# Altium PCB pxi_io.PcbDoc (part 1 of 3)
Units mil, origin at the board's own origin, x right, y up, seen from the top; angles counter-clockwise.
Board outline 6300 x 3935 mil, 2 copper layers (Top Layer, Bottom Layer); 271 components, 388 nets, 1544 pads, 249 vias.
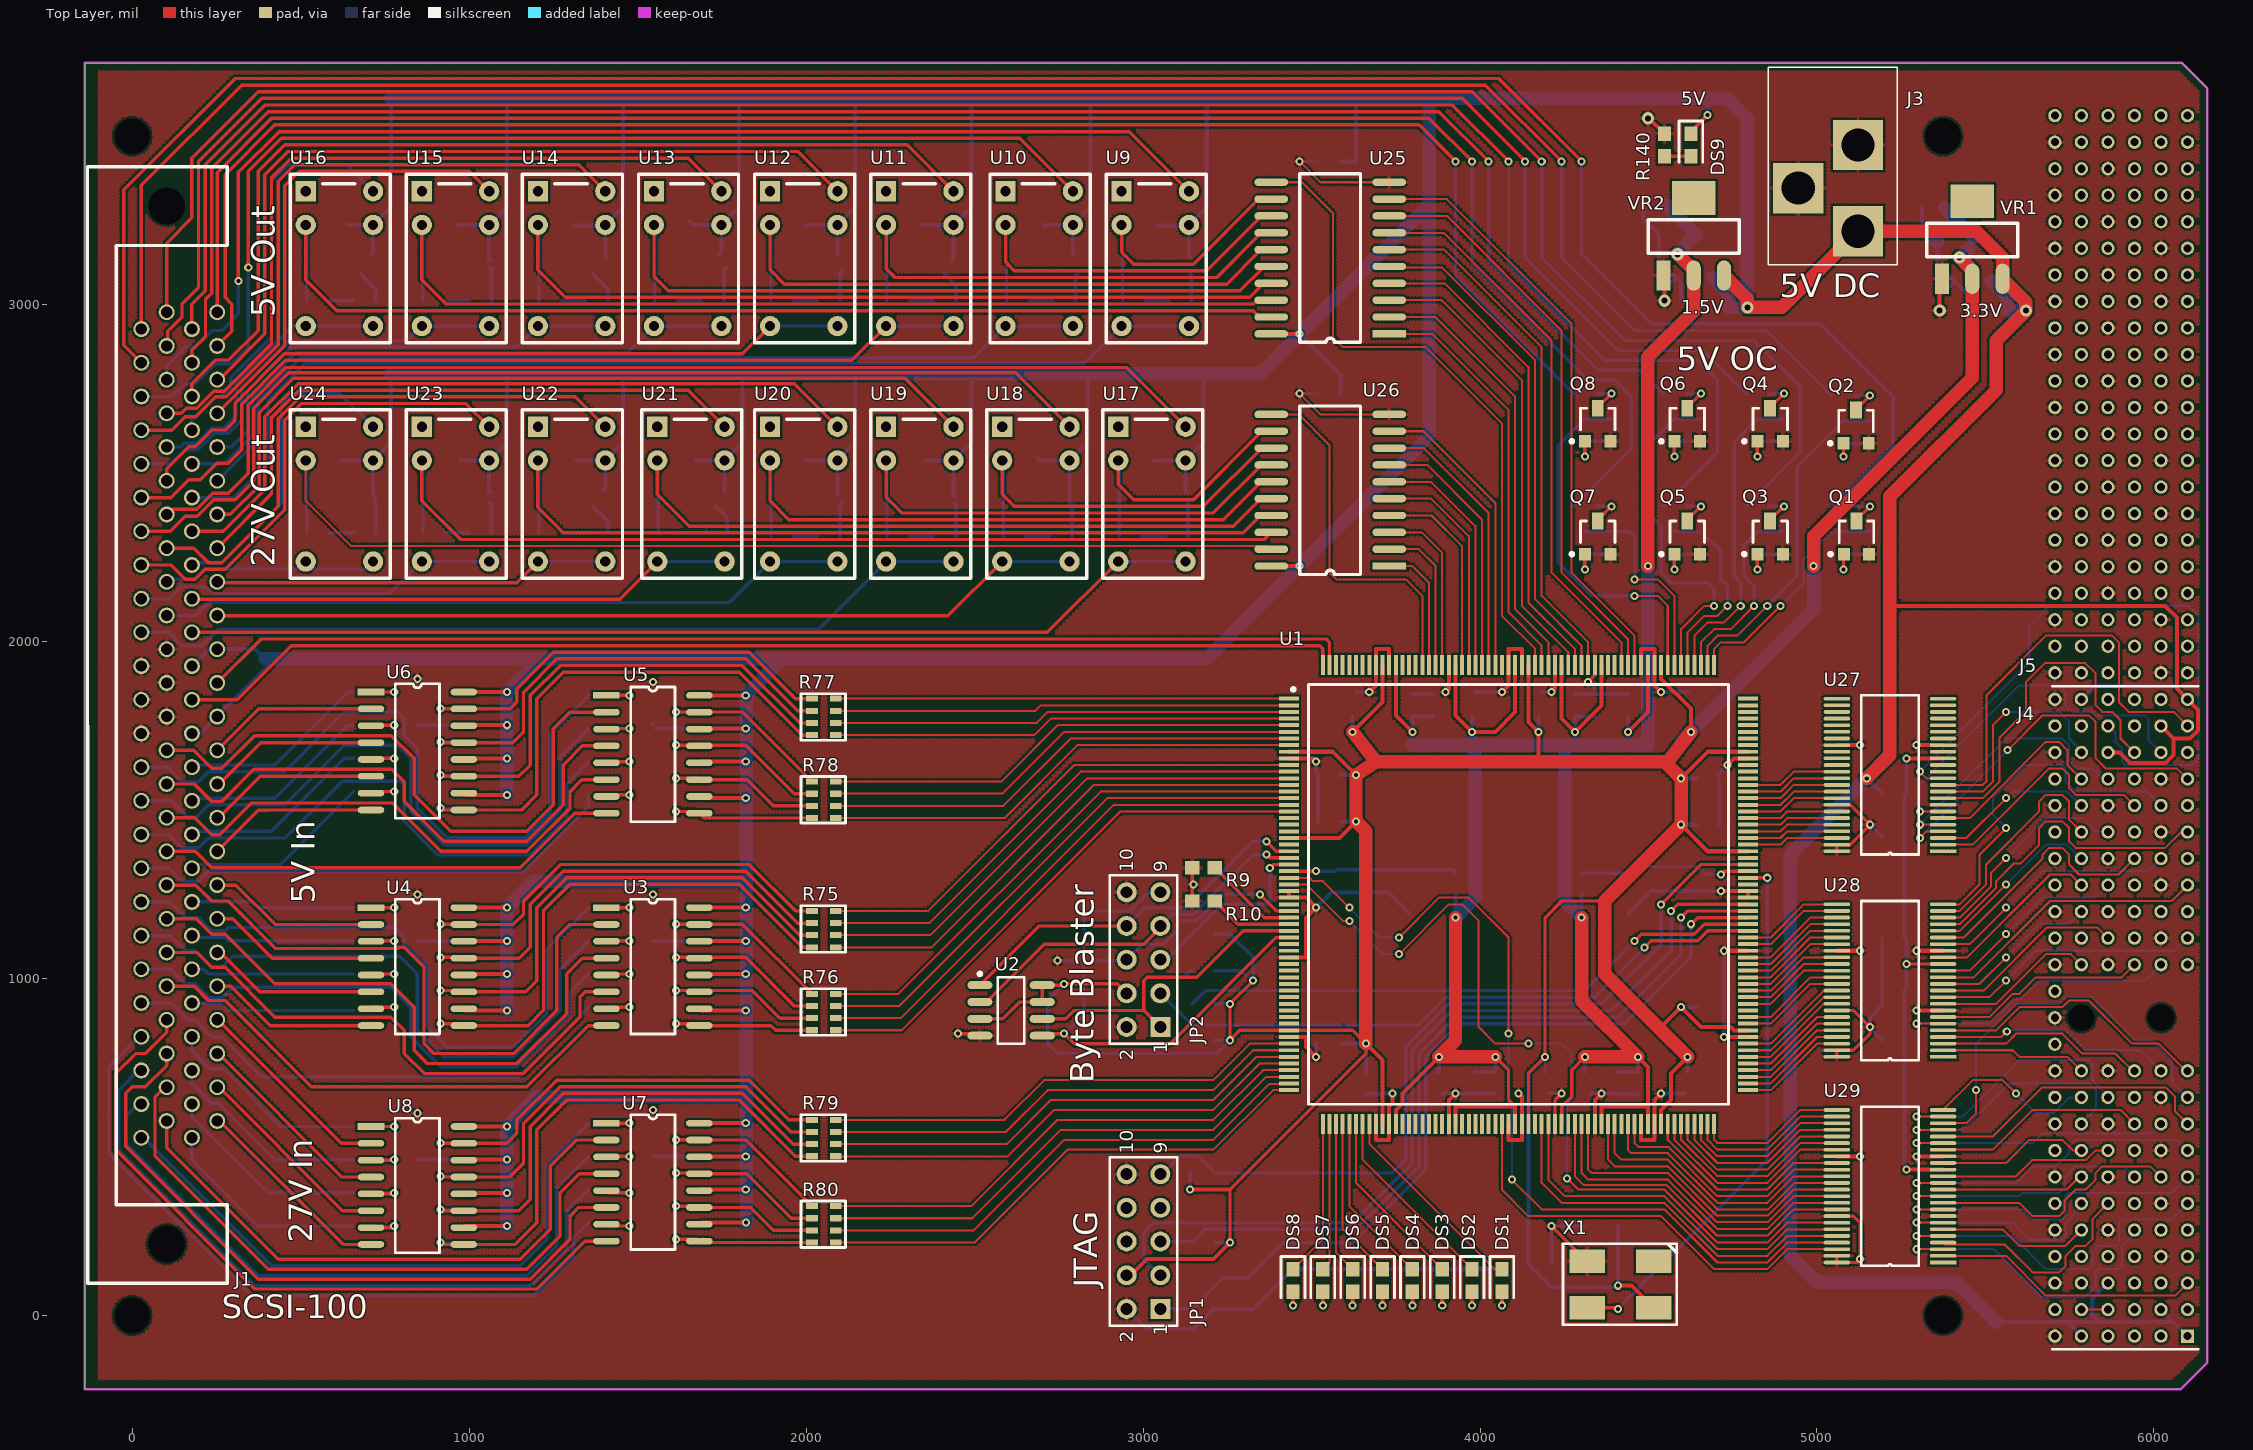
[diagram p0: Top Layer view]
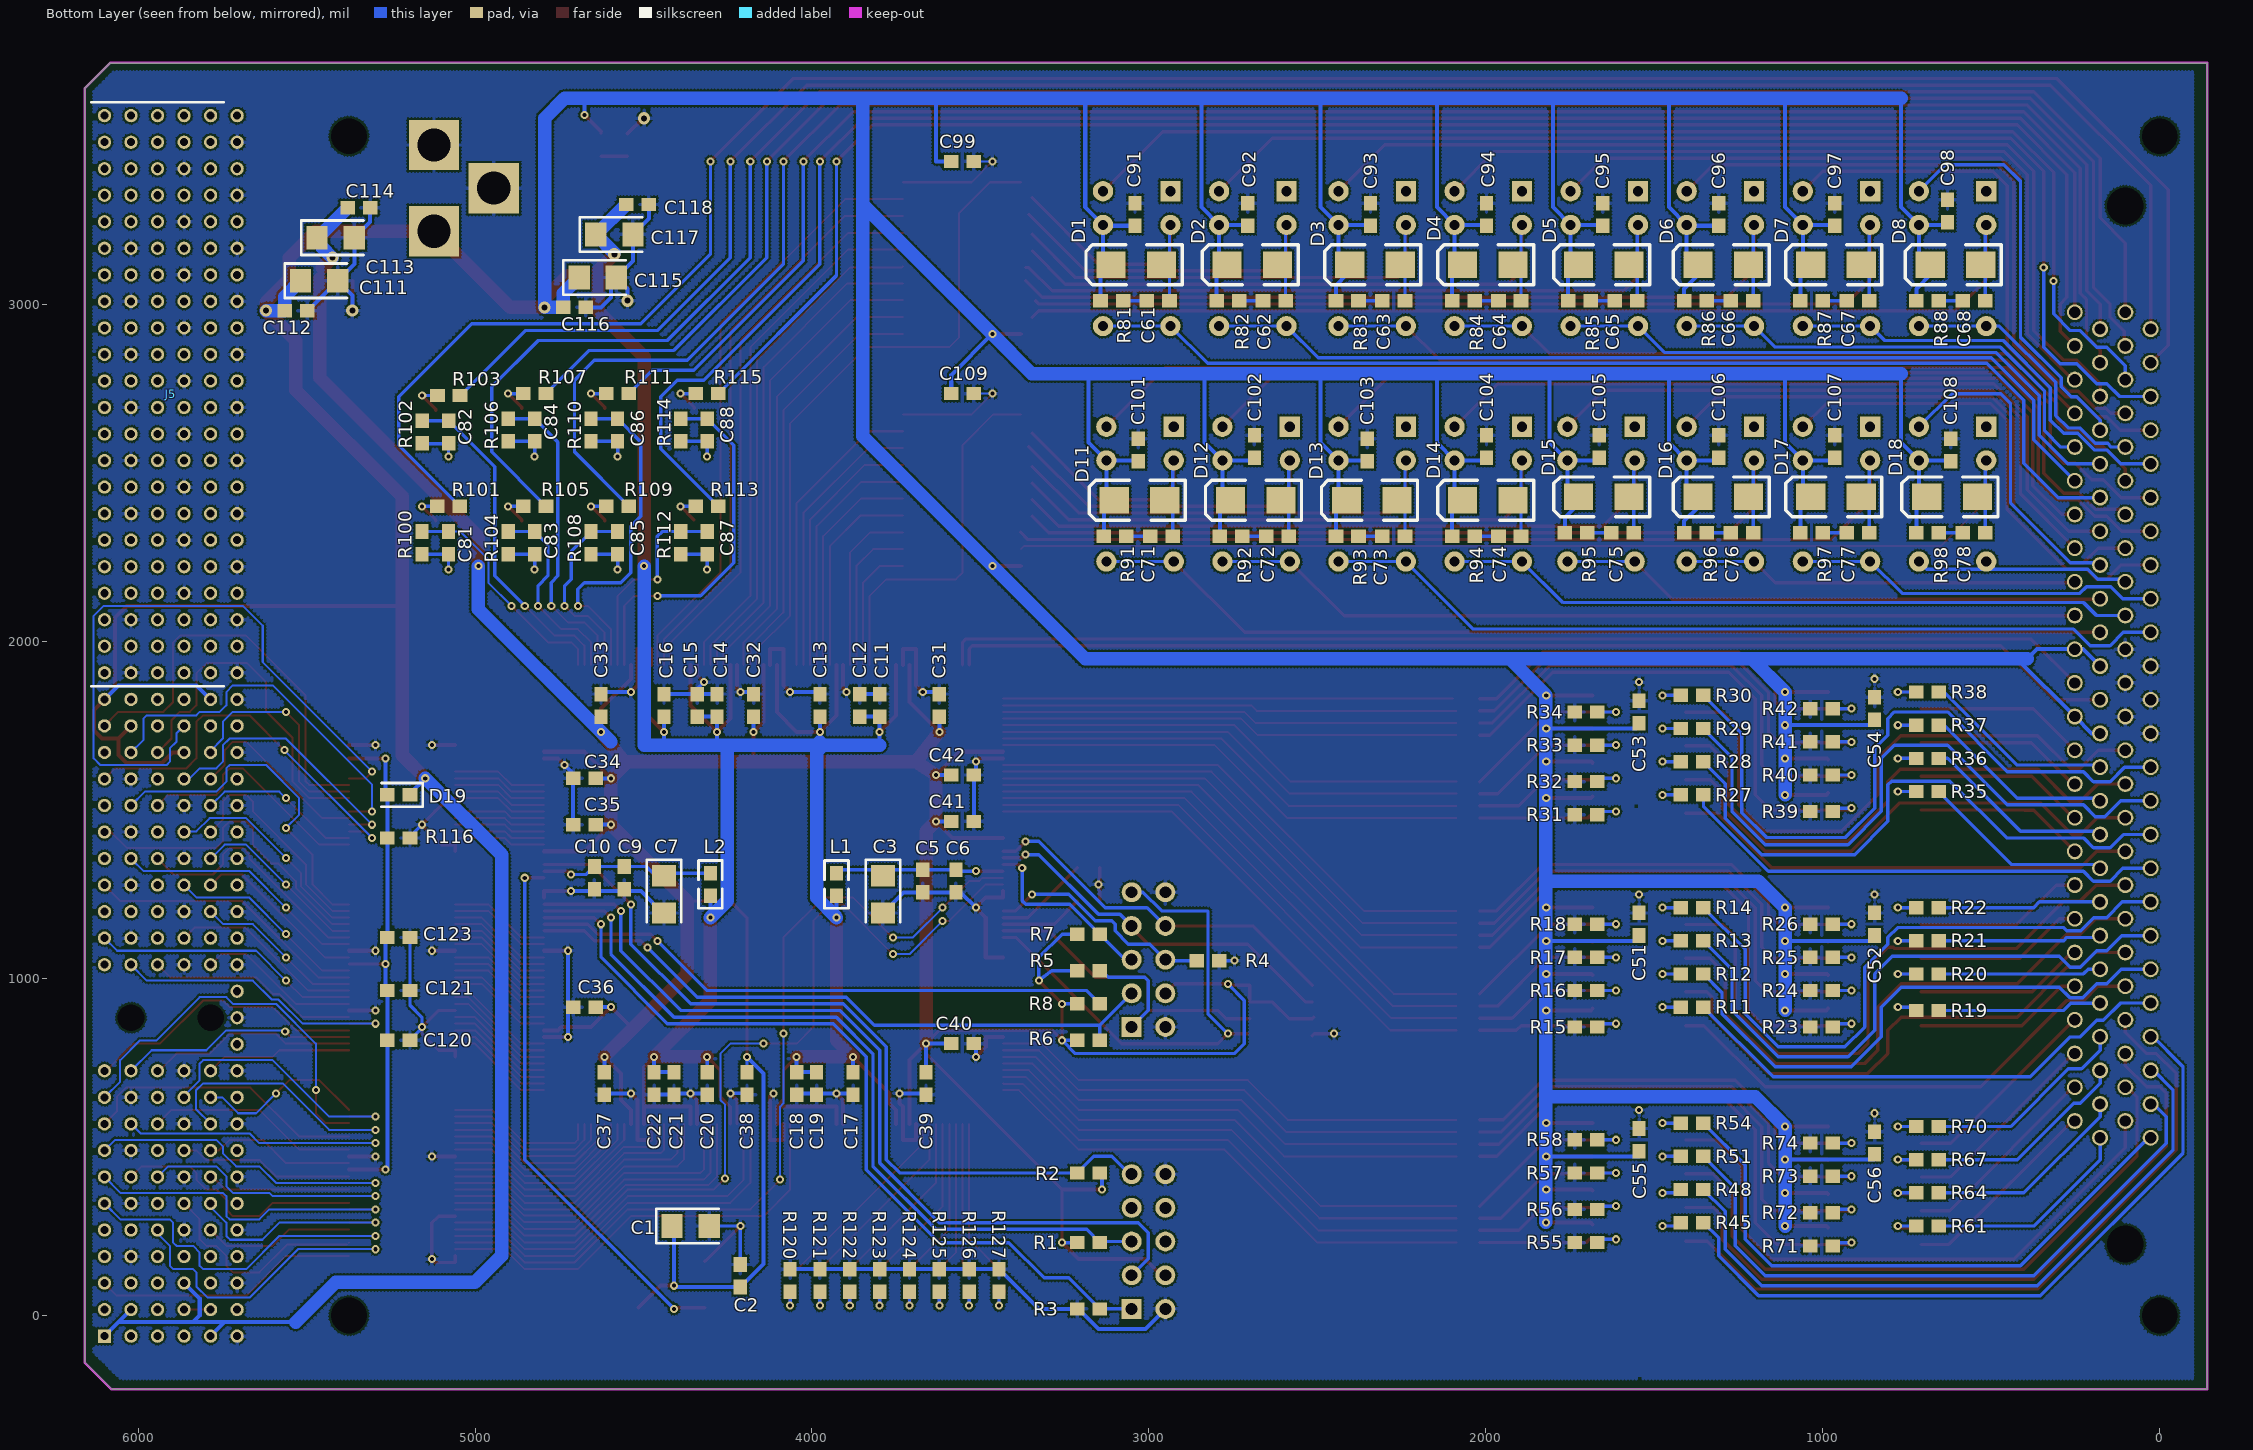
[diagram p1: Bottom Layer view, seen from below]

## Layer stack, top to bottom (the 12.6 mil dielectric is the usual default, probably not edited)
Top Layer: signal copper 1.4
Dielectric: core 12.6, FR-4, Dk 4.8
Bottom Layer: signal copper 1.4

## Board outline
-141.34,3717.05 6083.66,3717.05 6158.66,3642.05 6158.66,3637.05 6158.66,-137.95 6078.66,-217.95 -141.34,-217.95

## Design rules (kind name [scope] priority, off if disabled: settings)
Clearance [All] p1: gap=6
ComponentClearance [All] p1: gap=0 collisioncheckmode=3 verticalgap=10 showdistances=FALSE
FabricationTestPointUsage TestPointUsage [All] p1: valid=0 allowmultiple=FALSE
FabricationTestpoint Testpoint [All] p1: side=3 testpointundercomponent=TRUE minsize=40 maxsize=100 preferedsize=60 minholesize=0 maxholesize=40 preferedholesize=32 testpointgrid=1 allowsidetop=TRUE allowsidebottom=TRUE usegrid=TRUE gridtolerance=0.01
PolygonConnect [All] p1: connectstyle=Relief reliefconductorwidth=10 reliefentries=4 polygonreliefangle="90 Angle"
RoutingVias [All] p1: holewidth=28 width=50 viastyle="Through Hole" minholewidth=12 minwidth=24 maxholewidth=28 maxwidth=50
SilkscreenOverComponentPads [All] p1: minsilkscreentomaskgap=10
SolderMaskExpansion [All] p1: expansion=4
Width [All] p1: maxlimit=40 minlimit=6 preferedwidth=6
24 further rules are at their usual default settings.

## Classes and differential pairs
component class pxi_io: J1
component class pxi: C111 C112 C113 C114 C115 C116 C117 C118 C120 C121 C123 D19 DS9 J3 J4 J5 R116 R140 U27 U28 U29 VR1 VR2
component class fpga: C1 C2 C3 C5 C6 C7 C9 C10 C11 C12 C13 C14 C15 C16 C17 C18 C19 C20 C21 C22 C31 C32 C33 C34 C35 C36 C37 C38 C39 C40 C41 C42 DS1 DS2 DS3 DS4 DS5 DS6 DS7 DS8 JP1 JP2 L1 L2 R1 R2 R3 R4 R5 R6 R7 R8 R9 R10 R120 R121 R122 R123 R124 R125 R126 R127 U1 U2 X1
component class digit_out: C61 C62 C63 C64 C65 C66 C67 C68 C71 C72 C73 C74 C75 C76 C77 C78 C81 C82 C83 C84 C85 C86 C87 C88 C91 C92 C93 C94 C95 C96 C97 C98 C99 C101 C102 C103 C104 C105 C106 C107 C108 C109 D1 D2 D3 D4 D5 D6 D7 D8 D11 D12 D13 D14 D15 D16 D17 D18 Q1 Q2 Q3 Q4 Q5 Q6 Q7 Q8 R81 R82 R83 R84 R85 R86 R87 R88 R91 R92 R93 R94 R95 R96 R97 R98 R100 R101 R102 R103 R104 R105 R106 R107 R108 R109 R110 R111 R112 R113 R114 R115 U9 U10 U11 U12 U13 U14 U15 U16 U17 U18 U19 U20 U21 U22 U23 U24 U25 U26
component class digit_in: C51 C52 C53 C54 C55 C56 R11 R12 R13 R14 R15 R16 R17 R18 R19 R20 R21 R22 R23 R24 R25 R26 R27 R28 R29 R30 R31 R32 R33 R34 R35 R36 R37 R38 R39 R40 R41 R42 R45 R48 R51 R54 R55 R56 R57 R58 R61 R64 R67 R70 R71 R72 R73 R74 R75 R76 R77 R78 R79 R80 U3 U4 U5 U6 U7 U8

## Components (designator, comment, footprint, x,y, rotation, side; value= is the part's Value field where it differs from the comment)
C1 "Cap Pol3" CC3216-1206 4360.24,265.75 r180 bottom
C2 "Cap Semi" 1608[0603] 4212.6,118.11 r270 bottom
C3 "Cap Pol3" CC3216-1206 3789.37,1250 r270 bottom
C5 "Cap Semi" 1608[0603] 3671.26,1289.37 r90 bottom
C6 "Cap Semi" 1608[0603] 3572.83,1289.37 r90 bottom
C7 "Cap Pol3" CC3216-1206 4438.98,1250 r270 bottom
C9 "Cap Semi" 1608[0603] 4557.09,1299.21 r90 bottom
C10 "Cap Semi" 1608[0603] 4645.67,1299.21 r90 bottom
C11 "Cap Semi" 1608[0603] 3799.21,1811.02 r270 bottom
C12 "Cap Semi" 1608[0603] 3858.27,1811.02 r270 bottom
C13 "Cap Semi" 1608[0603] 3976.38,1811.02 r270 bottom
C14 "Cap Semi" 1608[0603] 4281.5,1811.02 r270 bottom
C15 "Cap Semi" 1608[0603] 4340.55,1811.02 r270 bottom
C16 "Cap Semi" 1608[0603] 4438.98,1811.02 r270 bottom
C17 "Cap Semi" 1608[0603] 3877.95,688.98 r90 bottom
C18 "Cap Semi" 1608[0603] 4045.28,688.98 r90 bottom
C19 "Cap Semi" 1608[0603] 3986.22,688.98 r90 bottom
C20 "Cap Semi" 1608[0603] 4311.02,688.98 r90 bottom
C21 "Cap Semi" 1608[0603] 4409.45,688.98 r90 bottom
C22 "Cap Semi" 1608[0603] 4468.5,688.98 r90 bottom
C31 "Cap Semi" 1608[0603] 3622.05,1811.02 r270 bottom
C32 "Cap Semi" 1608[0603] 4173.23,1811.02 r270 bottom
C33 "Cap Semi" 1608[0603] 4625.98,1811.02 r270 bottom
C34 "Cap Semi" 1608[0603] 4675.2,1594.49 r180 bottom
C35 "Cap Semi" 1608[0603] 4675.2,1456.69 r180 bottom
C36 "Cap Semi" 1608[0603] 4675.2,915.35 r180 bottom
C37 "Cap Semi" 1608[0603] 4616.14,688.98 r90 bottom
C38 "Cap Semi" 1608[0603] 4192.91,688.98 r90 bottom
C39 "Cap Semi" 1608[0603] 3661.42,688.98 r90 bottom
C40 "Cap Semi" 1608[0603] 3553.15,807.09 r0 bottom
C41 "Cap Semi" 1608[0603] 3553.15,1466.54 r0 bottom
C42 "Cap Semi" 1608[0603] 3553.15,1604.33 r0 bottom
C51 "Cap Semi" 1608[0603] 1545.28,1161.42 r270 bottom
C52 "Cap Semi" 1608[0603] 846.46,1161.42 r270 bottom
C53 "Cap Semi" 1608[0603] 1545.28,1791.34 r270 bottom
C54 "Cap Semi" 1608[0603] 846.46,1801.18 r270 bottom
C55 "Cap Semi" 1608[0603] 1545.28,521.65 r270 bottom
C56 "Cap Semi" 1608[0603] 846.46,511.81 r270 bottom
C61 "Cap Semi" 1608[0603] 2972.44,3011.81 r180 bottom
C62 "Cap Semi" 1608[0603] 2627.95,3011.81 r180 bottom
C63 "Cap Semi" 1608[0603] 2273.62,3011.81 r180 bottom
C64 "Cap Semi" 1608[0603] 1929.13,3011.81 r180 bottom
C65 "Cap Semi" 1608[0603] 1584.65,3011.81 r180 bottom
C66 "Cap Semi" 1608[0603] 1240.16,3011.81 r180 bottom
C67 "Cap Semi" 1608[0603] 895.67,3011.81 r180 bottom
C68 "Cap Semi" 1608[0603] 551.18,3011.81 r180 bottom
C71 "Cap Semi" 1608[0603] 2962.6,2312.99 r180 bottom
C72 "Cap Semi" 1608[0603] 2618.11,2312.99 r180 bottom
C73 "Cap Semi" 1608[0603] 2273.62,2312.99 r180 bottom
C74 "Cap Semi" 1608[0603] 1929.13,2312.99 r180 bottom
C75 "Cap Semi" 1608[0603] 1594.49,2322.83 r180 bottom
C76 "Cap Semi" 1608[0603] 1240.16,2322.83 r180 bottom
C77 "Cap Semi" 1608[0603] 895.67,2322.83 r180 bottom
C78 "Cap Semi" 1608[0603] 551.18,2322.83 r180 bottom
C81 "Cap Semi" 1608[0603] 5078.74,2293.31 r90 bottom
C82 "Cap Semi" 1608[0603] 5077.88,2622.1 r90 bottom
C83 "Cap Semi" 1608[0603] 4822.83,2293.31 r90 bottom
C84 "Cap Semi" 1608[0603] 4822.83,2627.95 r90 bottom
C85 "Cap Semi" 1608[0603] 4576.77,2293.31 r90 bottom
C86 "Cap Semi" 1608[0603] 4576.77,2627.95 r90 bottom
C87 "Cap Semi" 1608[0603] 4311.02,2293.31 r90 bottom
C88 "Cap Semi" 1608[0603] 4311.02,2627.95 r90 bottom
C91 "Cap Semi" 1608[0603] 3041.34,3267.72 r270 bottom
C92 "Cap Semi" 1608[0603] 2706.69,3267.72 r270 bottom
C93 "Cap Semi" 1608[0603] 2342.52,3267.72 r270 bottom
C94 "Cap Semi" 1608[0603] 1998.03,3267.72 r270 bottom
C95 "Cap Semi" 1608[0603] 1653.54,3267.72 r270 bottom
C96 "Cap Semi" 1608[0603] 1309.06,3267.72 r270 bottom
C97 "Cap Semi" 1608[0603] 964.57,3267.72 r270 bottom
C98 "Cap Semi" 1608[0603] 629.92,3277.56 r270 bottom
C99 "Cap Semi" 1608[0603] 3553.15,3425.2 r0 bottom
C101 "Cap Semi" 1608[0603] 3031.5,2568.9 r270 bottom
C102 "Cap Semi" 1608[0603] 2687.01,2578.74 r270 bottom
C103 "Cap Semi" 1608[0603] 2352.36,2568.9 r270 bottom
C104 "Cap Semi" 1608[0603] 1998.03,2578.74 r270 bottom
C105 "Cap Semi" 1608[0603] 1663.39,2578.74 r270 bottom
C106 "Cap Semi" 1608[0603] 1309.06,2578.74 r270 bottom
C107 "Cap Semi" 1608[0603] 964.57,2578.74 r270 bottom
C108 "Cap Semi" 1608[0603] 620.08,2568.9 r270 bottom
C109 "Cap Semi" 1608[0603] 3553.15,2736.22 r0 bottom
C111 "Cap Pol3" CC3216-1206 5462.6,3070.87 r180 bottom
C112 "Cap Semi" 1608[0603] 5531.5,2982.28 r0 bottom
C113 "Cap Pol3" CC3216-1206 5413.39,3198.82 r180 bottom
C114 "Cap Semi" 1608[0603] 5344.49,3287.4 r0 bottom
C115 "Cap Pol3" CC3216-1206 4635.83,3080.71 r180 bottom
C116 "Cap Semi" 1608[0603] 4704.72,2992.13 r0 bottom
C117 "Cap Pol3" CC3216-1206 4586.61,3208.66 r180 bottom
C118 "Cap Semi" 1608[0603] 4517.72,3297.24 r0 bottom
C120 "Cap Semi" 1608[0603] 5226.38,816.93 r0 bottom
C121 "Cap Semi" 1608[0603] 5226.38,964.57 r0 bottom
C123 "Cap Semi" 1608[0603] 5226.38,1122.05 r0 bottom
D1 "Diode" IN5817 2962.6,3218.5 r0 bottom
D2 "Diode" IN5817 2618.11,3218.5 r0 bottom
D3 "Diode" IN5817 2253.94,3218.5 r0 bottom
D4 "Diode" IN5817 1919.29,3218.5 r0 bottom
D5 "Diode" IN5817 1574.8,3218.5 r0 bottom
D6 "Diode" IN5817 1220.47,3218.5 r0 bottom
D7 "Diode" IN5817 885.83,3218.5 r0 bottom
D8 "Diode" IN5817 531.5,3218.5 r0 bottom
D11 "Diode" IN5817 2952.76,2519.69 r0 bottom
D12 "Diode" IN5817 2608.27,2519.69 r0 bottom
D13 "Diode" IN5817 2263.78,2519.69 r0 bottom
D14 "Diode" IN5817 1919.29,2519.69 r0 bottom
D15 "Diode" IN5817 1574.8,2529.53 r0 bottom
D16 "Diode" IN5817 1220.47,2529.53 r0 bottom
D17 "Diode" IN5817 885.83,2529.53 r0 bottom
D18 "Diode" IN5817 541.34,2529.53 r0 bottom
D19 "Diode" CC1608-0603 5226.38,1545.28 r0 bottom
DS1 "LED2" CC1608-0603 4064.96,104.33 r270 top
DS2 "LED2" CC1608-0603 3976.38,104.33 r270 top
DS3 "LED2" CC1608-0603 3887.8,104.33 r270 top
DS4 "LED2" CC1608-0603 3799.21,104.33 r270 top
DS5 "LED2" CC1608-0603 3710.63,104.33 r270 top
DS6 "LED2" CC1608-0603 3622.05,104.33 r270 top
DS7 "LED2" CC1608-0603 3533.46,104.33 r270 top
DS8 "LED2" CC1608-0603 3444.88,104.33 r270 top
DS9 "LED2" CC1608-0603 4625.98,3474.41 r270 top
J1 "Connector 100" SCSI-100 177.17,527.56 r90 top locked
J3 "PWP_CON" POWER_CON 5078.74,3503.94 r90 top locked
J4 "352068-1" BTB2-H135F 6099.61,-61.02 r90 top locked
J5 "352152-1" BTB2-H132FA 6099.61,1907.48 r270 bottom locked
JP1 "Header 5X2" HDR2X5 3051.18,19.68 r90 top
JP2 "Header 5X2" HDR2X5 3051.18,856.3 r90 top
L1 "Inductor" C1608-0603 3927.17,1279.53 r90 bottom
L2 "Inductor" C1608-0603 4301.18,1279.53 r90 bottom
Q1 "QNPN" SO3 5000,2500 r0 top
Q2 "QNPN" SO3 4999.14,2828.8 r0 top
Q3 "QNPN" SO3 4744.09,2500 r0 top
Q4 "QNPN" SO3 4744.09,2834.65 r0 top
Q5 "QNPN" SO3 4498.03,2500 r0 top
Q6 "QNPN" SO3 4498.03,2834.65 r0 top
Q7 "QNPN" SO3 4232.28,2500 r0 top
Q8 "QNPN" SO3 4232.28,2834.65 r0 top
R1 "Res Semi" 1608[0603] 3179.13,216.54 r0 bottom
R2 "Res Semi" 1608[0603] 3179.13,423.23 r180 bottom
R3 "Res Semi" 1608[0603] 3179.13,19.68 r0 bottom
R4 "Res Semi" 1608[0603] 2824.8,1053.15 r0 bottom
R5 "Res Semi" 1608[0603] 3179.13,1023.62 r180 bottom
R6 "Res Semi" 1608[0603] 3179.13,816.93 r180 bottom
R7 "Res Semi" 1608[0603] 3179.13,1131.89 r180 bottom
R8 "Res Semi" 1608[0603] 3179.13,925.2 r180 bottom
R9 "Res Semi" 1608[0603] 3179.13,1328.74 r180 top
R10 "Res Semi" 1608[0603] 3179.13,1230.32 r180 top
R11 "Res Semi" 1608[0603] 1387.8,915.35 r0 bottom
R12 "Res Semi" 1608[0603] 1387.8,1013.78 r0 bottom
R13 "Res Semi" 1608[0603] 1387.8,1112.2 r0 bottom
R14 "Res Semi" 1608[0603] 1387.8,1210.63 r0 bottom
R15 "Res Semi" 1608[0603] 1702.76,856.3 r0 bottom
R16 "Res Semi" 1608[0603] 1702.76,964.57 r0 bottom
R17 "Res Semi" 1608[0603] 1702.76,1062.99 r0 bottom
R18 "Res Semi" 1608[0603] 1702.76,1161.42 r0 bottom
R19 "Res Semi" 1608[0603] 688.98,905.51 r0 bottom
R20 "Res Semi" 1608[0603] 688.98,1013.78 r0 bottom
R21 "Res Semi" 1608[0603] 688.98,1112.2 r0 bottom
R22 "Res Semi" 1608[0603] 688.98,1210.63 r0 bottom
R23 "Res Semi" 1608[0603] 1003.94,856.3 r0 bottom
R24 "Res Semi" 1608[0603] 1003.94,964.57 r0 bottom
R25 "Res Semi" 1608[0603] 1003.94,1062.99 r0 bottom
R26 "Res Semi" 1608[0603] 1003.94,1161.42 r0 bottom
R27 "Res Semi" 1608[0603] 1387.8,1545.28 r0 bottom
R28 "Res Semi" 1608[0603] 1387.8,1643.7 r0 bottom
R29 "Res Semi" 1608[0603] 1387.8,1742.13 r0 bottom
R30 "Res Semi" 1608[0603] 1387.8,1840.55 r0 bottom
R31 "Res Semi" 1608[0603] 1702.76,1486.22 r0 bottom
R32 "Res Semi" 1608[0603] 1702.76,1584.65 r0 bottom
R33 "Res Semi" 1608[0603] 1702.76,1692.91 r0 bottom
R34 "Res Semi" 1608[0603] 1702.76,1791.34 r0 bottom
R35 "Res Semi" 1608[0603] 688.98,1555.12 r0 bottom
R36 "Res Semi" 1608[0603] 688.98,1653.54 r0 bottom
R37 "Res Semi" 1608[0603] 688.98,1751.97 r0 bottom
R38 "Res Semi" 1608[0603] 688.98,1850.39 r0 bottom
R39 "Res Semi" 1608[0603] 1003.94,1496.06 r0 bottom
R40 "Res Semi" 1608[0603] 1003.94,1604.33 r0 bottom
R41 "Res Semi" 1608[0603] 1003.94,1702.76 r0 bottom
R42 "Res Semi" 1608[0603] 1003.94,1801.18 r0 bottom
R45 "Res Semi" 1608[0603] 1387.8,275.59 r0 bottom
R48 "Res Semi" 1608[0603] 1387.8,374.02 r0 bottom
R51 "Res Semi" 1608[0603] 1387.8,472.44 r0 bottom
R54 "Res Semi" 1608[0603] 1387.8,570.87 r0 bottom
R55 "Res Semi" 1608[0603] 1702.76,216.54 r0 bottom
R56 "Res Semi" 1608[0603] 1702.76,314.96 r0 bottom
R57 "Res Semi" 1608[0603] 1702.76,423.23 r0 bottom
R58 "Res Semi" 1608[0603] 1702.76,521.65 r0 bottom
R61 "Res Semi" 1608[0603] 688.98,265.75 r0 bottom
R64 "Res Semi" 1608[0603] 688.98,364.17 r0 bottom
R67 "Res Semi" 1608[0603] 688.98,462.6 r0 bottom
R70 "Res Semi" 1608[0603] 688.98,561.02 r0 bottom
R71 "Res Semi" 1608[0603] 1003.94,206.69 r0 bottom
R72 "Res Semi" 1608[0603] 1003.94,305.12 r0 bottom
R73 "Res Semi" 1608[0603] 1003.94,413.39 r0 bottom
R74 "Res Semi" 1608[0603] 1003.94,511.81 r0 bottom
R75 "R0603_4" R0603_4 2017.72,1200.79 r0 top
R76 "R0603_4" R0603_4 2017.72,954.72 r0 top
R77 "R0603_4" R0603_4 2017.72,1830.71 r0 top
R78 "R0603_4" R0603_4 2017.72,1584.65 r0 top
R79 "R0603_4" R0603_4 2017.72,580.71 r0 top
R80 "R0603_4" R0603_4 2017.72,324.8 r0 top
R81 "Res Semi" 1608[0603] 3110.24,3011.81 r0 bottom
R82 "Res Semi" 1608[0603] 2765.75,3011.81 r0 bottom
R83 "Res Semi" 1608[0603] 2411.42,3011.81 r0 bottom
R84 "Res Semi" 1608[0603] 2066.93,3011.81 r0 bottom
R85 "Res Semi" 1608[0603] 1722.44,3011.81 r0 bottom
R86 "Res Semi" 1608[0603] 1377.95,3011.81 r0 bottom
R87 "Res Semi" 1608[0603] 1033.46,3011.81 r0 bottom
R88 "Res Semi" 1608[0603] 688.98,3011.81 r0 bottom
R91 "Res Semi" 1608[0603] 3100.39,2312.99 r0 bottom
R92 "Res Semi" 1608[0603] 2755.91,2312.99 r0 bottom
R93 "Res Semi" 1608[0603] 2411.42,2312.99 r0 bottom
R94 "Res Semi" 1608[0603] 2066.93,2312.99 r0 bottom
R95 "Res Semi" 1608[0603] 1732.28,2322.83 r0 bottom
R96 "Res Semi" 1608[0603] 1377.95,2322.83 r0 bottom
R97 "Res Semi" 1608[0603] 1033.46,2322.83 r0 bottom
R98 "Res Semi" 1608[0603] 688.98,2322.83 r0 bottom
R100 "Res Semi" 1608[0603] 5157.48,2293.31 r270 bottom
R101 "Res Semi" 1608[0603] 5078.74,2401.57 r180 bottom
R102 "Res Semi" 1608[0603] 5156.62,2622.1 r270 bottom
R103 "Res Semi" 1608[0603] 5077.88,2730.37 r180 bottom
R104 "Res Semi" 1608[0603] 4901.57,2293.31 r270 bottom
R105 "Res Semi" 1608[0603] 4822.83,2401.57 r180 bottom
R106 "Res Semi" 1608[0603] 4901.57,2627.95 r270 bottom
R107 "Res Semi" 1608[0603] 4822.83,2736.22 r180 bottom
R108 "Res Semi" 1608[0603] 4655.51,2293.31 r270 bottom
R109 "Res Semi" 1608[0603] 4576.77,2401.57 r180 bottom
R110 "Res Semi" 1608[0603] 4655.51,2627.95 r270 bottom
R111 "Res Semi" 1608[0603] 4576.77,2736.22 r180 bottom
R112 "Res Semi" 1608[0603] 4389.76,2293.31 r270 bottom
R113 "Res Semi" 1608[0603] 4311.02,2401.57 r180 bottom
R114 "Res Semi" 1608[0603] 4389.76,2627.95 r270 bottom
R115 "Res Semi" 1608[0603] 4311.02,2736.22 r180 bottom
R116 "Res Semi" 1608[0603] 5226.38,1417.32 r0 bottom
R120 "Res Semi" 1608[0603] 4064.96,104.33 r90 bottom
R121 "Res Semi" 1608[0603] 3976.38,104.33 r90 bottom
R122 "Res Semi" 1608[0603] 3887.8,104.33 r90 bottom
R123 "Res Semi" 1608[0603] 3799.21,104.33 r90 bottom
R124 "Res Semi" 1608[0603] 3710.63,104.33 r90 bottom
R125 "Res Semi" 1608[0603] 3622.05,104.33 r90 bottom
R126 "Res Semi" 1608[0603] 3533.46,104.33 r90 bottom
R127 "Res Semi" 1608[0603] 3444.88,104.33 r90 bottom
R140 "Res Semi" 1608[0603] 4547.24,3474.41 r270 top
U1 "EP1C12Q240C6" PQFP240 4114.17,1250 r0 top locked
U2 "EPCS1SI8" SOIC8_L 2608.27,905.51 r0 top
U3 "TLP281-4" TLP281-4 1407.48,1210.63 r0 top
U4 "TLP281-4" TLP281-4 708.66,1210.63 r0 top
U5 "TLP281-4" TLP281-4 1407.48,1840.55 r0 top
U6 "TLP281-4" TLP281-4 708.66,1850.39 r0 top
U7 "TLP281-4" TLP281-4 1407.48,570.87 r0 top
U8 "TLP281-4" TLP281-4 708.66,561.02 r0 top locked
U9 "G5V-1" G5V-1-DIP 2736.22,3336.61 r0 top
U10 "G5V-1" G5V-1-DIP 2391.73,3336.61 r0 top
U11 "G5V-1" G5V-1-DIP 2037.4,3336.61 r0 top
U12 "G5V-1" G5V-1-DIP 1692.91,3336.61 r0 top
U13 "G5V-1" G5V-1-DIP 1348.43,3336.61 r0 top
U14 "G5V-1" G5V-1-DIP 1003.94,3336.61 r0 top
U15 "G5V-1" G5V-1-DIP 659.45,3336.61 r0 top
U16 "G5V-1" G5V-1-DIP 314.96,3336.61 r0 top
U17 "G5V-1" G5V-1-DIP 2726.38,2637.8 r0 top
U18 "G5V-1" G5V-1-DIP 2381.89,2637.8 r0 top
U19 "G5V-1" G5V-1-DIP 2037.4,2637.8 r0 top
U20 "G5V-1" G5V-1-DIP 1692.91,2637.8 r0 top
U21 "G5V-1" G5V-1-DIP 1358.27,2637.8 r0 top
U22 "G5V-1" G5V-1-DIP 1003.94,2637.8 r0 top
U23 "G5V-1" G5V-1-DIP 659.45,2637.8 r0 top
U24 "G5V-1" G5V-1-DIP 314.96,2637.8 r0 top
U25 "74HC573" SOP20 3730.31,2913.39 r180 top
U26 "74HC573" SOP20 3730.31,2224.41 r180 top
U27 "SN74CBT16210" SSOP48 5374.02,1377.95 r180 top
U28 "SN74CBT16210" SSOP48 5374.02,767.72 r180 top
U29 "SN74CBT16210" SSOP48 5374.02,157.48 r180 top
VR1 "AS1117-3.3V" LM1117 5511.81,3326.77 r90 top locked
VR2 "AS1117-1.5V" LM1117 4685.04,3336.61 r90 top locked
X1 "OSCIL 50MHZ" "OSC -BIG" 4625.98,-68.9 r0 top

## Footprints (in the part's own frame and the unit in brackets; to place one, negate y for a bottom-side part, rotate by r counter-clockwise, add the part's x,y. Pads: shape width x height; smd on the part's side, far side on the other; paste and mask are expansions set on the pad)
1608[0603] [mm] "Chip Capacitor; Body 1.6 x 0.8 mm (LxW typ)"
  rect 1.1x1 smd: 1(-0.85,0) 2(0.85,0)
BTB2-H132FA [mm] "Board-to-Board Connector, Right Angle, Pitch 2mm, 132-Position, Female"
  round 1 hole 0.61: A1(0,0) A2(-2,0) A3(-4,0) A4(-6,0) A5(-8,0) A6(-10,0) A7(-12,0) A8(-14,0) A9(-16,0) A10(-18,0) A11(-20,0) A12(-22,0) A13(-24,0) A14(-26,0) A15(-28,0) A16(-30,0) A17(-32,0) A18(-34,0) A19(-36,0) A20(-38,0) A21(-40,0) A22(-42,0) B1(0,2) B2(-2,2) B3(-4,2) B4(-6,2) B5(-8,2) B6(-10,2) B7(-12,2) B8(-14,2) B9(-16,2) B10(-18,2) B11(-20,2) B12(-22,2) B13(-24,2) B14(-26,2) B15(-28,2) B16(-30,2) B17(-32,2) B18(-34,2) B19(-36,2) B20(-38,2) B21(-40,2) B22(-42,2) C1(0,4) C2(-2,4) C3(-4,4) C4(-6,4) C5(-8,4) C6(-10,4) C7(-12,4) C8(-14,4) C9(-16,4) C10(-18,4) C11(-20,4) C12(-22,4) C13(-24,4) C14(-26,4) C15(-28,4) C16(-30,4) C17(-32,4) C18(-34,4) C19(-36,4) C20(-38,4) C21(-40,4) C22(-42,4) D1(0,6) D2(-2,6) D3(-4,6) D4(-6,6) D5(-8,6) D6(-10,6) D7(-12,6) D8(-14,6) D9(-16,6) D10(-18,6) D11(-20,6) D12(-22,6) D13(-24,6) D14(-26,6) D15(-28,6) D16(-30,6) D17(-32,6) D18(-34,6) D19(-36,6) D20(-38,6) D21(-40,6) D22(-42,6) E1(0,8) E2(-2,8) E3(-4,8) E4(-6,8) E5(-8,8) E6(-10,8) E7(-12,8) E8(-14,8) E9(-16,8) E10(-18,8) E11(-20,8) E12(-22,8) E13(-24,8) E14(-26,8) E15(-28,8) E16(-30,8) E17(-32,8) E18(-34,8) E19(-36,8) E20(-38,8) E21(-40,8) E22(-42,8) F1(0,10) F2(-2,10) F3(-4,10) F4(-6,10) F5(-8,10) F6(-10,10) F7(-12,10) F8(-14,10) F9(-16,10) F10(-18,10) F11(-20,10) F12(-22,10) F13(-24,10) F14(-26,10) F15(-28,10) F16(-30,10) F17(-32,10) F18(-34,10) F19(-36,10) F20(-38,10) F21(-40,10) F22(-42,10)
  silkscreen extent -43,-1 1,9, body extent -43,-10.8 1,10.2, height 7.8
BTB2-H135F [mm] "Board-to-Board Connector, Right Angle, Pitch 2mm, 135-Position, Female"
  rect 1x1 hole 0.61: A1(0,0)
  round 1 hole 0.61: A2(2,0) A3(4,0) A4(6,0) A5(8,0) A6(10,0) A7(12,0) A8(14,0) A9(16,0) A10(18,0) A11(20,0) A15(28,0) A16(30,0) A17(32,0) A18(34,0) A19(36,0) A20(38,0) A21(40,0) A22(42,0) A23(44,0) A24(46,0) A25(48,0) B1(0,2) B2(2,2) B3(4,2) B4(6,2) B5(8,2) B6(10,2) B7(12,2) B8(14,2) B9(16,2) B10(18,2) B11(20,2) B15(28,2) B16(30,2) B17(32,2) B18(34,2) B19(36,2) B20(38,2) B21(40,2) B22(42,2) B23(44,2) B24(46,2) B25(48,2) C1(0,4) C2(2,4) C3(4,4) C4(6,4) C5(8,4) C6(10,4) C7(12,4) C8(14,4) C9(16,4) C10(18,4) C11(20,4) C15(28,4) C16(30,4) C17(32,4) C18(34,4) C19(36,4) C20(38,4) C21(40,4) C22(42,4) C23(44,4) C24(46,4) C25(48,4) D1(0,6) D2(2,6) D3(4,6) D4(6,6) D5(8,6) D6(10,6) D7(12,6) D8(14,6) D9(16,6) D10(18,6) D11(20,6) D15(28,6) D16(30,6) D17(32,6) D18(34,6) D19(36,6) D20(38,6) D21(40,6) D22(42,6) D23(44,6) D24(46,6) D25(48,6) E1(0,8) E2(2,8) E3(4,8) E4(6,8) E5(8,8) E6(10,8) E7(12,8) E8(14,8) E9(16,8) E10(18,8) E11(20,8) E15(28,8) E16(30,8) E17(32,8) E18(34,8) E19(36,8) E20(38,8) E21(40,8) E22(42,8) E23(44,8) E24(46,8) E25(48,8) F1(0,10) F2(2,10) F3(4,10) F4(6,10) F5(8,10) F6(10,10) F7(12,10) F8(14,10) F9(16,10) F10(18,10) F11(20,10) F12(22,10) F13(24,10) F14(26,10) F15(28,10) F16(30,10) F17(32,10) F18(34,10) F19(36,10) F20(38,10) F21(40,10) F22(42,10) F23(44,10) F24(46,10) F25(48,10)
  silkscreen extent -1,-0.8 49,10.2, body extent -0.95,-13.8 48.95,10.27, height 8.08
C1608-0603 [mm]
  rect 1.1x1 smd: 1(-0.85,0) 2(0.85,0)
  silkscreen extent -1.8,-0.9 1.8,0.9
CC1608-0603 [mm]
  rect 1.1x1 smd: 1(-0.85,0) 2(0.85,0)
  silkscreen extent -1.8,-0.9 1.3,0.9
CC3216-1206 [mm]
  rect 1.6x1.8 smd: 1(-1.4,0) 2(1.4,0)
  silkscreen extent -2.6,-1.3 2.1,1.3
G5V-1-DIP [mil]
  rect 60x60 hole 30: 1(200,0)
  round 60 hole 30: 2(200,-100) 5(200,-400) 6(400,-400) 9(400,-100) 10(400,0)
  silkscreen extent 154,-450 451,50
HDR2X5 [mm] "Connector; Header; 5x2 Position"
  rect 1.5x1.5 hole 0.9: 1(0,0)
  round 1.5 hole 0.9: 2(0,2.54) 3(2.54,0) 4(2.54,2.54) 5(5.08,0) 6(5.08,2.54) 7(7.62,0) 8(7.62,2.54) 9(10.16,0) 10(10.16,2.54)
  silkscreen extent -1.27,-1.27 11.43,3.81
IN5817 [mm]
  rect 2.2x2 smd: 1(0,2.54) 2(3.81,2.54)
  silkscreen extent -1.55,1.04 5.69,4.04
LM1117 [mil]
  rect 90x42 smd: 1(-250,141)
  oval 90x42 smd: 2(-250,51) 3(-250,-39)
  rect 100x130 smd: 4(-20,51)
  silkscreen extent -184,-84 -85,186
"OSC -BIG" [mil]
  rect 105x70 smd: 1(-111,230) 2(-307.85,230) 3(-308,92) 4(-111,92.2)
  silkscreen extent -380,42 -42,282
POWER_CON [mm]
  rect 3.8x3.8 hole 2.5: 1(-7.264,-1.092) 2(-0.764,-1.092) 3(-4.014,3.408)
  silkscreen extent -9.8,-4.06 5.08,5.69
PQFP240 [mm] "byTX chaned for cyclone FPGA"
  rect 1.5x0.3 smd: 1(-17.3,14.75) 2(-17.3,14.25) 3(-17.3,13.75) 4(-17.3,13.25) 5(-17.3,12.75) 6(-17.3,12.25) 7(-17.3,11.75) 8(-17.3,11.25) 9(-17.3,10.75) 10(-17.3,10.25) 11(-17.3,9.75) 12(-17.3,9.25) 13(-17.3,8.75) 14(-17.3,8.25) 15(-17.3,7.75) 16(-17.3,7.25) 17(-17.3,6.75) 18(-17.3,6.25) 19(-17.3,5.75) 20(-17.3,5.25) 21(-17.3,4.75) 22(-17.3,4.25) 23(-17.3,3.75) 24(-17.3,3.25) 25(-17.3,2.75) 26(-17.3,2.25) 27(-17.3,1.75) 28(-17.3,1.25) 29(-17.3,0.75) 30(-17.3,0.25) 31(-17.3,-0.25) 32(-17.3,-0.75) 33(-17.3,-1.25) 34(-17.3,-1.75) 35(-17.3,-2.25) 36(-17.3,-2.75) 37(-17.3,-3.25) 38(-17.3,-3.75) 39(-17.3,-4.25) 40(-17.3,-4.75) 41(-17.3,-5.25) 42(-17.3,-5.75) 43(-17.3,-6.25) 44(-17.3,-6.75) 45(-17.3,-7.25) 46(-17.3,-7.75) 47(-17.3,-8.25) 48(-17.3,-8.75) 49(-17.3,-9.25) 50(-17.3,-9.75) 51(-17.3,-10.25) 52(-17.3,-10.75) 53(-17.3,-11.25) 54(-17.3,-11.75) 55(-17.3,-12.25) 56(-17.3,-12.75) 57(-17.3,-13.25) 58(-17.3,-13.75) 59(-17.3,-14.25) 60(-17.3,-14.75) 121(17.3,-14.75) 122(17.3,-14.25) 123(17.3,-13.75) 124(17.3,-13.25) 125(17.3,-12.75) 126(17.3,-12.25) 127(17.3,-11.75) 128(17.3,-11.25) 129(17.3,-10.75) 130(17.3,-10.25) 131(17.3,-9.75) 132(17.3,-9.25) 133(17.3,-8.75) 134(17.3,-8.25) 135(17.3,-7.75) 136(17.3,-7.25) 137(17.3,-6.75) 138(17.3,-6.25) 139(17.3,-5.75) 140(17.3,-5.25) 141(17.3,-4.75) 142(17.3,-4.25) 143(17.3,-3.75) 144(17.3,-3.25) 145(17.3,-2.75) 146(17.3,-2.25) 147(17.3,-1.75) 148(17.3,-1.25) 149(17.3,-0.75) 150(17.3,-0.25) 151(17.3,0.25) 152(17.3,0.75) 153(17.3,1.25) 154(17.3,1.75) 155(17.3,2.25) 156(17.3,2.75) 157(17.3,3.25) 158(17.3,3.75) 159(17.3,4.25) 160(17.3,4.75) 161(17.3,5.25) 162(17.3,5.75) 163(17.3,6.25) 164(17.3,6.75) 165(17.3,7.25) 166(17.3,7.75) 167(17.3,8.25) 168(17.3,8.75) 169(17.3,9.25) 170(17.3,9.75) 171(17.3,10.25) 172(17.3,10.75) 173(17.3,11.25) 174(17.3,11.75) 175(17.3,12.25) 176(17.3,12.75) 177(17.3,13.25) 178(17.3,13.75) 179(17.3,14.25) 180(17.3,14.75)
  rect 0.3x1.5 smd: 61(-14.75,-17.3) 62(-14.25,-17.3) 63(-13.75,-17.3) 64(-13.25,-17.3) 65(-12.75,-17.3) 66(-12.25,-17.3) 67(-11.75,-17.3) 68(-11.25,-17.3) 69(-10.75,-17.3) 70(-10.25,-17.3) 71(-9.75,-17.3) 72(-9.25,-17.3) 73(-8.75,-17.3) 74(-8.25,-17.3) 75(-7.75,-17.3) 76(-7.25,-17.3) 77(-6.75,-17.3) 78(-6.25,-17.3) 79(-5.75,-17.3) 80(-5.25,-17.3) 81(-4.75,-17.3) 82(-4.25,-17.3) 83(-3.75,-17.3) 84(-3.25,-17.3) 85(-2.75,-17.3) 86(-2.25,-17.3) 87(-1.75,-17.3) 88(-1.25,-17.3) 89(-0.75,-17.3) 90(-0.25,-17.3) 91(0.25,-17.3) 92(0.75,-17.3) 93(1.25,-17.3) 94(1.75,-17.3) 95(2.25,-17.3) 96(2.75,-17.3) 97(3.25,-17.3) 98(3.75,-17.3) 99(4.25,-17.3) 100(4.75,-17.3) 101(5.25,-17.3) 102(5.75,-17.3) 103(6.25,-17.3) 104(6.75,-17.3) 105(7.25,-17.3) 106(7.75,-17.3) 107(8.25,-17.3) 108(8.75,-17.3) 109(9.25,-17.3) 110(9.75,-17.3) 111(10.25,-17.3) 112(10.75,-17.3) 113(11.25,-17.3) 114(11.75,-17.3) 115(12.25,-17.3) 116(12.75,-17.3) 117(13.25,-17.3) 118(13.75,-17.3) 119(14.25,-17.3) 120(14.75,-17.3) 181(14.75,17.3) 182(14.25,17.3) 183(13.75,17.3) 184(13.25,17.3) 185(12.75,17.3) 186(12.25,17.3) 187(11.75,17.3) 188(11.25,17.3) 189(10.75,17.3) 190(10.25,17.3) 191(9.75,17.3) 192(9.25,17.3) 193(8.75,17.3) 194(8.25,17.3) 195(7.75,17.3) 196(7.25,17.3) 197(6.75,17.3) 198(6.25,17.3) 199(5.75,17.3) 200(5.25,17.3) 201(4.75,17.3) 202(4.25,17.3) 203(3.75,17.3) 204(3.25,17.3) 205(2.75,17.3) 206(2.25,17.3) 207(1.75,17.3) 208(1.25,17.3) 209(0.75,17.3) 210(0.25,17.3) 211(-0.25,17.3) 212(-0.75,17.3) 213(-1.25,17.3) 214(-1.75,17.3) 215(-2.25,17.3) 216(-2.75,17.3) 217(-3.25,17.3) 218(-3.75,17.3) 219(-4.25,17.3) 220(-4.75,17.3) 221(-5.25,17.3) 222(-5.75,17.3) 223(-6.25,17.3) 224(-6.75,17.3) 225(-7.25,17.3) 226(-7.75,17.3) 227(-8.25,17.3) 228(-8.75,17.3) 229(-9.25,17.3) 230(-9.75,17.3) 231(-10.25,17.3) 232(-10.75,17.3) 233(-11.25,17.3) 234(-11.75,17.3) 235(-12.25,17.3) 236(-12.75,17.3) 237(-13.25,17.3) 238(-13.75,17.3) 239(-14.25,17.3) 240(-14.75,17.3)
  silkscreen extent -17.1,-15.83 15.83,15.83
R0603_4 [mil] "for ResPackX4____OK!"
  rect 35x18 smd: 1(0,0) 2(0,-36) 3(0,-72) 4(0,-108) 5(70.16,-108) 6(70.16,-72) 7(70.16,-36) 8(70.16,0)
  silkscreen extent -33,-123 99,15
SCSI-100 [mm]
  round 1.2 hole 0.85: 1(0,0) 2(1.27,-1.905) 3(2.54,0) 4(3.81,-1.905) 5(5.08,0) 6(6.35,-1.905) 7(7.62,0) 8(8.89,-1.905) 9(10.16,0) 10(11.43,-1.905) 11(12.7,0) 12(13.97,-1.905) 13(15.24,0) 14(16.51,-1.905) 15(17.78,0) 16(19.05,-1.905) 17(20.32,0) 18(21.59,-1.905) 19(22.86,0) 20(24.13,-1.905) 21(25.4,0) 22(26.67,-1.905) 23(27.94,0) 24(29.21,-1.905) 25(30.48,0) 26(31.75,-1.905) 27(33.02,0) 28(34.29,-1.905) 29(35.56,0) 30(36.83,-1.905) 31(38.1,0) 32(39.37,-1.905) 33(40.64,0) 34(41.91,-1.905) 35(43.18,0) 36(44.45,-1.905) 37(45.72,0) 38(46.99,-1.905) 39(48.26,0) 40(49.53,-1.905) 41(50.8,0) 42(52.07,-1.905) 43(53.34,0) 44(54.61,-1.905) 45(55.88,0) 46(57.15,-1.905) 47(58.42,0) 48(59.69,-1.905) 49(60.96,0) 50(62.23,-1.905) 51(0,3.81) 52(1.27,1.905) 53(2.54,3.81) 54(3.81,1.905) 55(5.08,3.81) 56(6.35,1.905) 57(7.62,3.81) 58(8.89,1.905) 59(10.16,3.81) 60(11.43,1.905) 61(12.7,3.81) 62(13.97,1.905) 63(15.24,3.81) 64(16.51,1.905) 65(17.78,3.81) 66(19.05,1.905) 67(20.32,3.81) 68(21.59,1.905) 69(22.86,3.81) 70(24.13,1.905) 71(25.4,3.81) 72(26.67,1.905) 73(27.94,3.81) 74(29.21,1.905) 75(30.48,3.81) 76(31.75,1.905) 77(33.02,3.81) 78(34.29,1.905) 79(35.56,3.81) 80(36.83,1.905) 81(38.1,3.81) 82(39.37,1.905) 83(40.64,3.81) 84(41.91,1.905) 85(43.18,3.81) 86(44.45,1.905) 87(45.72,3.81) 88(46.99,1.905) 89(48.26,3.81) 90(49.53,1.905) 91(50.8,3.81) 92(52.07,1.905) 93(53.34,3.81) 94(54.61,1.905) 95(55.88,3.81) 96(57.15,1.905) 97(58.42,3.81) 98(59.69,1.905) 99(60.96,3.81) 100(62.23,1.905)
  round 2.5 hole 2.77: 101(-8.01,1.905) 102(70.24,1.905)
  silkscreen extent -10.97,-2.67 73.2,7.87
SO3 [mm]
  rect 0.9x1.27 smd: 1(2.972,-3.601)
  rect 0.9x0.95 smd: 2(2.022,-6.101) 3(3.922,-6.101)
  silkscreen extent 0.9,-6.23 4.27,-3.6
SOIC8_L [mm] "SOIC, 8-Leads, Body 4.9x3.9mm, Pitch 1.27mm, IPC High Density"
  oval 1.9x0.6 smd: 1(-2.35,1.905) 2(-2.35,0.635) 3(-2.35,-0.635) 4(-2.35,-1.905) 5(2.35,-1.905) 6(2.35,-0.635) 7(2.35,0.635) 8(2.35,1.905)
  silkscreen extent -2.47,-2.5 1,2.88, body extent -1.95,-2.45 1.95,2.45, height 1.75
SOP20 [mil]
  rect 100x22 smd: 1(0,0)
  oval 100x22 smd: 2(0,-50) 3(0,-100) 4(0,-150) 5(0,-200) 6(0,-250) 7(0,-300) 8(0,-350) 9(0,-400) 10(0,-450) 11(350,-450) 12(350,-400) 13(350,-350) 14(350,-300) 15(350,-250) 16(350,-200) 17(350,-150) 18(350,-100) 19(350,-50) 20(350,0)
  silkscreen extent 85,-475 265,25
SSOP48 [mm]
  rect 2x0.28 smd: 1(0,0)
  oval 2x0.28 smd: 2(0,-0.5) 3(0,-1) 4(0,-1.5) 5(0,-2) 6(0,-2.5) 7(0,-3) 8(0,-3.5) 9(0,-4) 10(0,-4.5) 11(0,-5) 12(0,-5.5) 13(0,-6) 14(0,-6.5) 15(0,-7) 16(0,-7.5) 17(0,-8) 18(0,-8.5) 19(0,-9) 20(0,-9.5) 21(0,-10) 22(0,-10.5) 23(0,-11) 24(0,-11.5) 25(8,-11.5) 26(8,-11) 27(8,-10.5) 28(8,-10) 29(8,-9.5) 30(8,-9) 31(8,-8.5) 32(8,-8) 33(8,-7.5) 34(8,-7) 35(8,-6.5) 36(8,-6) 37(8,-5.5) 38(8,-5) 39(8,-4.5) 40(8,-4) 41(8,-3.5) 42(8,-3) 43(8,-2.5) 44(8,-2) 45(8,-1.5) 46(8,-1) 47(8,-0.5) 48(8,0)
  silkscreen extent 1.84,-11.75 6.16,0.25
TLP281-4 [mm]
  rect 2x0.5 smd: 1(0,0)
  oval 2x0.5 smd: 2(0,-1.27) 3(0,-2.54) 4(0,-3.81) 5(0,-5.08) 6(0,-6.35) 7(0,-7.62) 8(0,-8.89) 9(7,-8.89) 10(7,-7.62) 11(7,-6.35) 12(7,-5.08) 13(7,-3.81) 14(7,-2.54) 15(7,-1.27) 16(7,0)
  silkscreen extent 1.84,-9.53 5.17,0.64

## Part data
C1 C3 C7 C111 C113 C115 C117: "Polarized Capacitor (Surface Mount)"
C2 C5 C6 C9 C10 C11 C12 C13 C14 C15 C16 C17 C18 C19 C20 C21 C22 C31 C32 C33 C34 C35 C36 C37 C38 C39 C40 C41 C42 C51 C52 C53 C54 C55 C56 C61 C62 C63 C64 C65 C66 C67 C68 C71 C72 C73 C74 C75 C76 C77 C78 C81 C82 C83 C84 C85 C86 C87 C88 C91 C92 C93 C94 C95 C96 C97 C98 C99 C101 C102 C103 C104 C105 C106 C107 C108 C109 C112 C114 C116 C118 C120 C121 C123: "Capacitor (Semiconductor SIM Model)"
D1 D2 D3 D4 D5 D6 D7 D8 D11 D12 D13 D14 D15 D16 D17 D18 D19: "Default Diode"
DS1 DS2 DS3 DS4 DS5 DS6 DS7 DS8 DS9: "Typical RED, GREEN, YELLOW, AMBER GaAs LED"
J1: "Receptacle Header Assemby"
J4: "Z-Pack 2mm Hard Metric Type A 110 Position Female PCB Mount Connector"
J5: "Z-Pack 2mm Hard Metric Type B 110 Position Female Daughter Card Connector"
JP1 JP2: "Header, 5-Pin, Dual row"
Q1 Q2 Q3 Q4 Q5 Q6 Q7 Q8: "NPN Bipolar Transistor"
R1 R2 R3 R4 R5 R6 R7 R8 R9 R10 R11 R12 R13 R14 R15 R16 R17 R18 R19 R20 R21 R22 R23 R24 R25 R26 R27 R28 R29 R30 R31 R32 R33 R34 R35 R36 R37 R38 R39 R40 R41 R42 R45 R48 R51 R54 R55 R56 R57 R58 R61 R64 R67 R70 R71 R72 R73 R74 R81 R82 R83 R84 R85 R86 R87 R88 R91 R92 R93 R94 R95 R96 R97 R98 R100 R101 R102 R103 R104 R105 R106 R107 R108 R109 R110 R111 R112 R113 R114 R115 R116 R120 R121 R122 R123 R124 R125 R126 R127 R140: "Semiconductor Resistor"
R75 R76 R77 R78 R79 R80: "Resistor Array - Parts"
U1: "Cyclone Family, 1.5V FPGA, 173 I/O Pins, 2 x PLLs, Commercial Grade, Speed Grade 6"
U2: "EPCS1 Series, In-system programmable 3.3V serial configuration device, 8-Pin SOIC, 1-Megabit, Industrial Grade"
VR1 VR2: library part "Volt Reg", "Voltage Regulator"
X1: library part OSCIL

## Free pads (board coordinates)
  round 94.49 hole 106.3 unplated: MH1(0,0) MH2(0,3500) MH3(5374.02,0) MH4(5374.02,3500)
  round 66.93 hole 78.74 unplated: MH5(5784.65,883.86) MH6(6020.87,883.86)

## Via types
v1: diameter 24, hole 12, Top Layer to Bottom Layer, 241 vias
v2: diameter 36, hole 18, Top Layer to Bottom Layer, 7 vias
v3: diameter 24, hole 12, Top Layer to Bottom Layer, tented bottom, 1 vias

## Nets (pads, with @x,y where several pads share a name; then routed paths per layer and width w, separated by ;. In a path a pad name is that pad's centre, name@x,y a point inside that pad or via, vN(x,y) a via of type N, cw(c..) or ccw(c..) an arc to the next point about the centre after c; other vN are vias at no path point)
1.5V: C11.2 C12.2 C13.2 C14.2 C15.2 C16.2 C17.2 C18.2 C19.2 C20.2 C21.2 C22.2 C117.1 C118.2 L1.1 L2.1 U1.72 U1.81 U1.90 U1.97 U1.103 U1.110 U1.191 U1.198 U1.204 U1.211 U1.220 U1.229 VR2.2 | length 8405.1
  Top Layer w10: v1(3976.38,1732.28) 3996.06,1732.28 ; v1(4045.28,767.72) 4084.65,728.35 4084.65,639.76 4104.33,620.08 ; U1.97@4242.13,568.9 4242.13,620.08 4271.65,649.61 4271.65,728.35 v1(4311.02,767.72) ; VR2.2@4634.04,3086.61 VR2.2@4634.04,3102.18
  Top Layer w12: U1.72@3750,568.9 3750,610.24 3769.69,629.92 3769.69,659.45 v1(3877.95,767.72) ; U1.229@3750,1931.1 3750,1781.5 v1(3799.21,1732.28) ; U1.81@3927.17,568.9 3927.17,620.08 4104.33,620.08 U1.90@4104.33,568.9 ; U1.220@3927.17,1931.1 3927.17,1781.5 v1(3976.38,1732.28) 4045.28,1732.28 4104.33,1791.34 U1.211@4104.33,1931.1 ; U1.204@4242.13,1931.1 4242.13,1771.65 v1(4281.5,1732.28) 4360.24,1811.02 U1.198@4360.24,1931.1 ; U1.103@4360.24,568.9 4360.24,620.08 4498.03,620.08 ; v1(4438.98,1732.28) 4498.03,1791.34 U1.191@4498.03,1931.1 ; v1(4468.5,767.72) 4498.03,738.19 4498.03,620.08 ; U1.110@4498.03,568.9 4498.03,620.08
  Top Layer w40: v1(3927.17,1181.1) 3927.17,816.93 v1(3877.95,767.72) v1(4045.28,767.72) ; v1(4301.18,1181.1) 4301.18,935.04 v1(4468.5,767.72) v1(4311.02,767.72) ; v1(4498.03,2224.41) 4498.03,2844.49 4634.04,2980.5 VR2.2@4634.04,3086.61 ; v2(4586.61,3149.61) VR2.2@4634.04,3102.18
  Bottom Layer w10: C20.2@4311.02,722.44 v1(4311.02,767.72) ; v2(4586.61,3149.61) v2@4586.61,3153.54 ; C117.1@4639.76,3208.66 C117.1@4641.73,3208.66
  Bottom Layer w12: 3799.21,1692.91 v1(3799.21,1732.28) C11.2@3799.21,1777.56 C12.2@3858.27,1777.56 ; C17.2@3877.95,722.44 v1(3877.95,767.72) ; v1(3927.17,1181.1) L1.1@3927.17,1246.06 ; 3976.38,1692.91 3976.38,1702.76 v1(3976.38,1732.28) C13.2@3976.38,1777.56 ; C19.2@3986.22,722.44 C18.2@4045.28,722.44 v1(4045.28,767.72) ; 4281.5,1692.91 v1(4281.5,1732.28) C14.2@4281.5,1777.56 C15.2@4340.55,1777.56 ; v1(4301.18,1181.1) L2.1@4301.18,1246.06 ; C21.2@4409.45,722.44 C22.2@4468.5,722.44 v1(4468.5,767.72) ; 4438.98,1692.91 v1(4438.98,1732.28) C16.2@4438.98,1777.56
  Bottom Layer w40: 3799.21,1692.91 3966.54,1692.91 ; v1(3927.17,1181.1) 3986.22,1240.16 3986.22,1673.23 3966.54,1692.91 ; 3976.38,1702.76 3976.38,1692.91 ; v1(4301.18,1181.1) 4251.97,1230.31 4251.97,1692.91 ; v1(4498.03,2224.41) 4498.03,1692.91 4251.97,1692.91 ; C118.2@4551.18,3297.24 C117.1@4639.76,3208.66 ; v2@4586.61,3153.54 C117.1@4641.73,3208.66 ; 3966.54,1692.91 3976.38,1692.91 ; 3976.38,1692.91 4251.97,1692.91
3.3V: C1.1 C2.2 C31.2 C32.2 C33.2 C34.2 C35.2 C36.2 C37.2 C38.2 C39.2 C40.2 C41.2 C42.2 C113.1 C114.2 JP1.4 JP2.4 R1.2 R2.2 R5.1 R6.1 R7.1 R8.1 U1.9 U1.22 U1.51 U1.70 U1.92 U1.112 U1.130 U1.157 U1.172 U1.189 U1.209 U1.231 U2.3 U2.7 U2.8 VR1.2 X1.4 | length 13841.6
  Top Layer w10: U2.3@2510.43,885.83 U2.3@2515.75,880.51 2583.27,880.51 2633.27,930.51 U2.7@2700.79,930.51 U2.8@2700.79,980.51 v1@2762.01,980.51 ; v1(2765.75,984.25) 2923.23,984.25 JP2.4@2951.18,956.3 ; v1(3257.87,216.54) 3257.87,374.02 3661.42,777.56 v1(3661.42,807.09) 3622.05,846.46 U1.51@3433.07,846.46 3287.4,846.46 v1(3257.87,816.93) v1(3257.87,925.2) v1(3326.77,994.09) ; U1.92@4143.7,568.9 4143.7,718.5 v1(4192.91,767.72) 4192.91,1181.1 4242.13,1230.31 4370.08,1230.31 ; VR1.2@5452.76,3100.39 VR1.2@5452.76,3110.24
  Top Layer w12: JP1.4@2951.18,119.68 2964.17,119.68 3011.81,167.32 3208.66,167.32 v1(3257.87,216.54) ; v1(3139.76,374.02) 3257.87,374.02 ; U1.22@3433.07,1417.32 3582.68,1417.32 v1(3631.89,1466.54) ; U1.9@3433.07,1673.23 3562.99,1673.23 v1(3631.89,1604.33) ; v1(3622.05,1732.28) 3710.63,1820.87 U1.231@3710.63,1931.1 ; v1(3661.42,807.09) 3710.63,757.87 U1.70@3710.63,568.9 ; U1.209@4143.7,1931.1 4143.7,1761.81 v1(4173.23,1732.28) 4173.23,1663.39 ; v1(4409.45,88.58) 4449.71,88.58 X1.4@4514.98,23.31 ; 4530.34,853.51 4534.62,853.51 v1(4596.46,915.35) 4655.51,856.3 4744.09,856.3 4753.94,846.46 U1.130@4795.28,846.46 ; U1.112@4537.4,568.9 4537.4,610.24 4566.93,639.76 4566.93,718.5 v1(4616.14,767.72) ; U1.189@4537.4,1931.1 4537.4,1889.76 4625.98,1801.18 v1(4625.98,1732.28) ; v1(4596.46,1456.69) 4675.2,1377.95 U1.157@4795.28,1377.95 ; v1(4596.46,1594.49) 4675.2,1673.23 U1.172@4795.28,1673.23
  Top Layer w40: v1(3622.05,1732.28) 3690.94,1643.7 ; v1(3661.42,807.09) 3661.42,1437.01 v1(3631.89,1466.54) v1(3631.89,1604.33) 3690.94,1643.7 ; v1(4616.14,767.72) 4530.34,853.51 4370.08,1013.78 4370.08,1230.31 v1(4596.46,1456.69) v1(4596.46,1594.49) 4557.09,1633.86 4557.09,1643.7 ; v1(4625.98,1732.28) 4557.09,1643.7 ; v1(4990.16,2224.41) 4990.16,2312.99 5460.81,2783.65 VR1.2@5460.81,3076.77 ; v2(5423.23,3139.76) VR1.2@5452.76,3110.24 ; 3690.94,1643.7 4557.09,1643.7
  Bottom Layer w10: v1(2765.75,984.25) 2716.54,935.04 2716.54,807.09 2746.06,777.56 3218.5,777.56 v1(3257.87,816.93) R6.1@3212.6,816.93 ; R1.2@3212.6,216.54 v1(3257.87,216.54) ; R8.1@3212.6,925.2 v1(3257.87,925.2) ; R5.1@3212.6,1023.62 3287.4,1023.62 v1(3326.77,994.09) 3326.77,1062.99 3257.87,1131.89 R7.1@3212.6,1131.89 ; C39.2@3661.42,718.5 C39.2@3661.42,722.44 ; C38.2@4192.91,722.44 v1(4192.91,767.72) ; C113.1@5452.76,3169.29 C113.1@5452.76,3179.13 ; C113.1@5466.54,3198.82 C113.1@5468.5,3198.82
  Bottom Layer w12: v1(3139.76,374.02) R2.2@3139.76,423.23 ; C41.2@3586.61,1466.54 v1(3631.89,1466.54) ; C42.2@3586.61,1604.33 v1(3631.89,1604.33) ; C40.2@3592.52,807.09 v1(3661.42,807.09) C39.2@3661.42,722.44 ; v1(3622.05,1732.28) C31.2@3622.05,1777.56 ; v1(4173.23,1732.28) C32.2@4173.23,1777.56 ; v1(4192.91,767.72) 4143.7,718.5 4143.7,153.54 C2.2@4212.6,84.65 4405.51,84.65 v1(4409.45,88.58) C1.1@4409.45,265.75 ; v1(4596.46,915.35) C36.2@4641.73,915.35 ; v1(4596.46,1456.69) C35.2@4641.73,1456.69 ; v1(4596.46,1594.49) C34.2@4641.73,1594.49 ; C37.2@4616.14,722.44 v1(4616.14,767.72) ; v1(4625.98,1732.28) C33.2@4625.98,1777.56
  Bottom Layer w40: 4596.46,1702.76 v1(4625.98,1732.28) 4990.16,2096.46 v1(4990.16,2224.41) ; C114.2@5377.95,3287.4 C113.1@5466.54,3198.82 ; v2(5423.23,3139.76) C113.1@5452.76,3169.29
